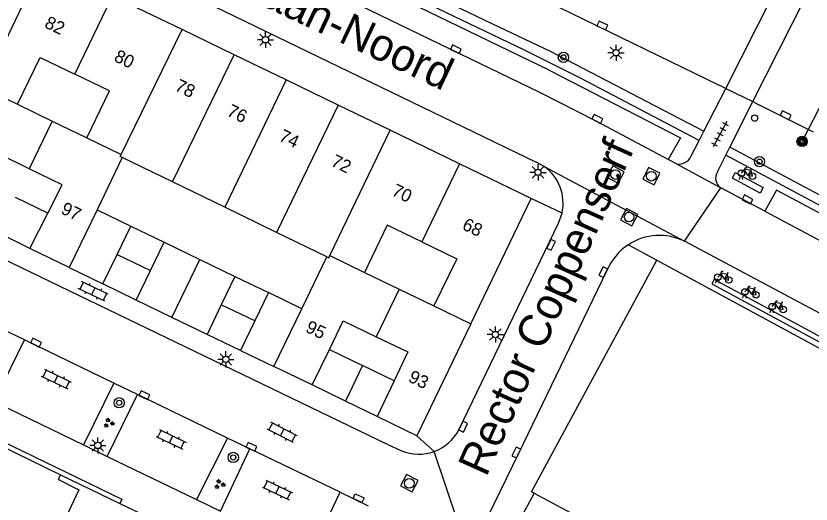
# Model space of a CAD drawing. Extents: x 132999 to 136000, y 398499 to 400501.
# Drawn here: x 134215 to 134276.8, y 398577.7 to 398615.7 of the extents above; entities that cross this region are included whole.
import ezdxf

# ---------------------------------------------------------------- set-up
doc = ezdxf.new("R2010")
doc.units = 0
for name, color, linetype in [('gg-afsc-muur', 7, 'Continuous'), ('gg-anno-huisnummerreeks BGT', 7, 'Continuous'), ('gg-anno-openbare ruimte label', 7, 'Continuous'), ('gg-bbg-bijgebouw', 7, 'Continuous'), ('gg-bbg-gedigitaliseerde bebouwing', 7, 'Continuous'), ('gg-bbg-gedigitaliseerde bijgebouw', 7, 'Continuous'), ('gg-bbg-hoofdgebouw', 7, 'Continuous'), ('gg-bbg-luifel en loopbrug', 7, 'Continuous'), ('gg-bbg-tussenscheiding', 7, 'Continuous'), ('gg-knt-verharding', 7, 'Continuous'), ('gg-knt-verharding nz', 7, 'Continuous'), ('gt-grn-groengrens', 7, 'Continuous'), ('gt-grn-weggrens', 7, 'Continuous'), ('gt-knt-lijn portaal', 7, 'Continuous'), ('gt-symb-boom', 7, 'Continuous'), ('gt-symb-fietsenrek', 7, 'Continuous'), ('gt-symb-groenvak', 7, 'Continuous'), ('gt-symb-klinker verharding', 7, 'Continuous'), ('gt-symb-kolk', 7, 'Continuous'), ('gt-symb-kolk center center', 7, 'Continuous'), ('gt-symb-lichtmast', 7, 'Continuous'), ('gt-symb-portaalmast', 7, 'Continuous'), ('gt-symb-rioolschacht', 7, 'Continuous'), ('gt-symb-tegel verharding', 7, 'Continuous'), ('gt-symb-verkeersregelinstallatiepaal', 7, 'Continuous')]:
    doc.layers.add(name, color=color, linetype=linetype)

# ---------------------------------------------------------------- blocks, each defined once
blk = doc.blocks.new('gt0-KOLK')
at = {"layer": 'gt-symb-kolk'}
blk.add_lwpolyline([(0, 0), (0.375, 0), (0.375, 0.4), (-0.375, 0.4), (-0.375, 0), (0, 0)], dxfattribs=at)
blk = doc.blocks.new('gt0-KL1')
at = {"layer": 'gt-symb-klinker verharding'}
for p, q in [((-1.15, 0.3), (1.15, 0.3)), ((-1, -0.3), (-1, 0.3)), ((-0.5, 0.3), (-0.5, 0.45)), ((0, -0.3), (0, 0.3)), ((0.5, 0.3), (0.5, 0.45)), ((1, -0.3), (1, 0.3)), ((-1.15, -0.3), (1.15, -0.3)), ((-0.5, -0.45), (-0.5, -0.3)), ((0.5, -0.45), (0.5, -0.3))]:
    blk.add_line(p, q, dxfattribs=at)
blk = doc.blocks.new('gt0-LMAST')
at = {"layer": 'gt-symb-lichtmast'}
for p, q in [((-0.005, 0.246), (-0.005, 0.621)), ((-0.182, 0.173), (-0.447, 0.438)), ((0.172, 0.173), (0.437, 0.438)), ((-0.255, -0.004), (-0.63, -0.004)), ((-0.182, -0.181), (-0.447, -0.446)), ((-0.005, -0.254), (-0.005, -0.629)), ((0.437, -0.446), (0.172, -0.181)), ((0.245, -0.004), (0.62, -0.004))]:
    blk.add_line(p, q, dxfattribs=at)
blk.add_circle((-0.005, -0.004), 0.25, dxfattribs=at)
blk = doc.blocks.new('gt0-GRVAK')
at = {"layer": 'gt-symb-groenvak'}
for p, q in [((-0.11, 0.189), (-0.228, 0.24)), ((-0.182, 0.153), (0.088, 0.153)), ((-0.091, 0.211), (-0.156, 0.322)), ((-0.047, 0.214), (-0.047, 0.393)), ((-0.004, 0.211), (0.061, 0.322)), ((0.015, 0.189), (0.133, 0.24)), ((0.262, -0.052), (0.197, 0.059)), ((0.305, -0.049), (0.305, 0.13)), ((0.349, -0.052), (0.414, 0.059)), ((-0.245, -0.228), (-0.363, -0.177)), ((-0.318, -0.264), (-0.047, -0.264)), ((-0.226, -0.206), (-0.291, -0.095)), ((-0.183, -0.203), (-0.183, -0.024)), ((-0.139, -0.206), (-0.074, -0.095)), ((-0.12, -0.228), (-0.002, -0.177)), ((0.243, -0.074), (0.125, -0.023)), ((0.17, -0.11), (0.441, -0.11)), ((0.368, -0.074), (0.486, -0.023))]:
    blk.add_line(p, q, dxfattribs=at)
blk = doc.blocks.new('gt0-BOOM')
at = {"layer": 'gt-symb-boom'}
for radius in [0.4, 0.2]:
    blk.add_circle((0, 0), radius, dxfattribs=at)
blk = doc.blocks.new('gt0-PORTM')
at = {"layer": 'gt-symb-portaalmast'}
for radius in [0.4, 0.33, 0.27, 0.21, 0.15]:
    blk.add_circle((0, 0), radius, dxfattribs=at)
blk = doc.blocks.new('gt0-TEG1')
at = {"layer": 'gt-symb-tegel verharding'}
for p, q in [((-1.125, 0), (1.125, 0)), ((-0.9, -0.25), (-0.9, 0.25)), ((-0.45, -0.25), (-0.45, 0.25)), ((0, -0.25), (0, 0.25)), ((0.45, -0.25), (0.45, 0.25)), ((0.9, -0.25), (0.9, 0.25))]:
    blk.add_line(p, q, dxfattribs=at)
blk = doc.blocks.new('gt0-FREK')
at = {"layer": 'gt-symb-fietsenrek'}
for p, q in [((0.259, 0.762), (0.294, 0.823)), ((0.54, 0.335), (0.259, 0.762)), ((0.294, 0.823), (0.767, 0.714)), ((0.767, 0.714), (0.54, 0.335)), ((0.757, 0.841), (0.866, 0.816)), ((0.767, 0.714), (0.84, 0.822)), ((0.895, 0.252), (0.767, 0.714))]:
    blk.add_line(p, q, dxfattribs=at)
for points in [[(0.036, 0.476), (0.228, 0.708), (0.259, 0.762)], [(0.294, 0.823), (0.36, 0.937), (0.452, 0.935)], [(-0.124, 0), (-0.047, 0.312), (0.053, 0.312), (0.12, 0)], [(0.54, 0.335), (0.555, 0.305), (0.895, 0.252)]]:
    blk.add_lwpolyline(points, dxfattribs=at)
for centre in [(0.036, 0.476), (0.895, 0.252)]:
    blk.add_circle(centre, 0.252, dxfattribs=at)
blk = doc.blocks.new('gt0-VIPAAL')
at = {"layer": 'gt-symb-verkeersregelinstallatiepaal'}
blk.add_circle((0, 0), 0.25, dxfattribs=at)
blk = doc.blocks.new('gt0-RS')
at = {"layer": 'gt-symb-rioolschacht'}
blk.add_lwpolyline([(-0.5, -0.5), (0.5, -0.5), (0.5, 0.5), (-0.5, 0.5)], close=True, dxfattribs=at)
blk.add_circle((0, 0), 0.375, dxfattribs=at)
blk = doc.blocks.new('gt0-KOLKCC')
at = {"layer": 'gt-symb-kolk center center'}
blk.add_lwpolyline([(-0.375, 0.2), (0.375, 0.2), (0.375, -0.2), (-0.375, -0.2)], close=True, dxfattribs=at)

msp = doc.modelspace()

# ---------------------------------------------------------------- linework, layer by layer
at = {"layer": 'gg-afsc-muur'}
for p, q in [((134218.437, 398579.968), (134223.046, 398577.746)), ((134223.046, 398577.746), (134224.741, 398576.929))]:
    msp.add_line(p, q, dxfattribs=at)
at = {"layer": 'gg-bbg-bijgebouw'}
for p, q in [((134217.447, 398600.328), (134214.917, 398601.556)), ((134222.838, 398597.119), (134223.9, 398599.316)), ((134223.9, 398599.316), (134226.497, 398598.061)), ((134216.054, 398597.583), (134213.575, 398598.785)), ((134221.724, 398594.814), (134222.838, 398597.119)), ((134232.007, 398595.398), (134234.609, 398594.14)), ((134224.321, 398593.558), (134221.724, 398594.814)), ((134234.609, 398594.14), (134233.547, 398591.943)), ((134233.547, 398591.943), (134232.433, 398589.637)), ((134232.433, 398589.637), (134229.831, 398590.895)), ((134239.35, 398589.721), (134241.929, 398588.47)), ((134244.387, 398587.276), (134241.929, 398588.47)), ((134240.594, 398585.707), (134238.025, 398586.956)), ((134243.063, 398584.513), (134240.594, 398585.707))]:
    msp.add_line(p, q, dxfattribs=at)
at = {"layer": 'gg-bbg-gedigitaliseerde bebouwing'}
for p, q in [((134215.092, 398608.801), (134217.791, 398607.491)), ((134217.791, 398607.491), (134220.49, 398606.181)), ((134242.09, 398595.718), (134244.791, 398594.413)), ((134244.791, 398594.413), (134247.492, 398593.108))]:
    msp.add_line(p, q, dxfattribs=at)
for points in [[(134215.092, 398608.801), (134216.845, 398612.441), (134219.546, 398611.136)], [(134220.49, 398606.181), (134222.247, 398609.831), (134219.546, 398611.136)], [(134246.558, 398598.084), (134243.857, 398599.389), (134242.09, 398595.718)], [(134246.558, 398598.084), (134249.26, 398596.779), (134247.492, 398593.108)]]:
    msp.add_lwpolyline(points, dxfattribs=at)
at = {"layer": 'gg-bbg-gedigitaliseerde bijgebouw'}
for p, q in [((134225.435, 398595.863), (134226.497, 398598.061)), ((134224.321, 398593.558), (134225.435, 398595.863)), ((134232.007, 398595.398), (134230.945, 398593.2)), ((134230.945, 398593.2), (134229.831, 398590.895))]:
    msp.add_line(p, q, dxfattribs=at)
at = {"layer": 'gg-bbg-hoofdgebouw'}
for p, q in [((134227.885, 398614.602), (134222.474, 398617.218)), ((134231.937, 398612.644), (134227.885, 398614.602)), ((134235.989, 398610.686), (134231.937, 398612.644)), ((134240.031, 398608.732), (134235.989, 398610.686)), ((134244.082, 398606.774), (134240.031, 398608.732)), ((134249.485, 398604.163), (134244.082, 398606.774)), ((134223.233, 398604.65), (134221.273, 398600.585)), ((134227.155, 398602.75), (134223.233, 398604.65)), ((134255.058, 398601.469), (134249.485, 398604.163)), ((134231.219, 398600.781), (134227.155, 398602.75)), ((134250.364, 398591.72), (134255.058, 398601.469)), ((134221.273, 398600.585), (134219.112, 398596.103)), ((134235.245, 398598.831), (134231.219, 398600.781)), ((134239.152, 398596.938), (134235.245, 398598.831)), ((134219.112, 398596.103), (134216.054, 398597.583)), ((134237.199, 398592.888), (134239.152, 398596.938)), ((134264.827, 398596.655), (134298.563, 398578.435)), ((134235.032, 398588.395), (134237.199, 398592.888)), ((134250.364, 398591.72), (134246.17, 398583.009)), ((134238.025, 398586.956), (134235.032, 398588.395)), ((134246.17, 398583.009), (134243.063, 398584.513)), ((134213.622, 398582.293), (134218.437, 398579.968)), ((134218.262, 398579.605), (134218.437, 398579.968))]:
    msp.add_line(p, q, dxfattribs=at)
for points in [[(134215.996, 398603.785), (134213.594, 398604.946), (134212.475, 398602.741)], [(134217.447, 398600.328), (134218.57, 398602.54), (134215.996, 398603.785)], [(134255.28, 398578.547), (134255.08, 398578.655), (134264.827, 398596.655)], [(134239.35, 398589.721), (134240.415, 398591.944), (134243.004, 398590.703)], [(134243.004, 398590.703), (134245.464, 398589.524), (134244.387, 398587.276)], [(134218.262, 398579.605), (134219.852, 398578.812), (134216.922, 398572.55), (134215.246, 398573.36)], [(134255.28, 398578.547), (134264.765, 398573.446), (134263.402, 398570.93), (134268.388, 398568.238), (134269.734, 398570.761), (134274.256, 398568.307), (134272.919, 398565.793), (134277.893, 398563.137), (134279.228, 398565.625), (134288.714, 398560.516)]]:
    msp.add_lwpolyline(points, dxfattribs=at)
at = {"layer": 'gg-bbg-luifel en loopbrug'}
for p, q in [((134221.273, 398600.585), (134223.9, 398599.316)), ((134226.497, 398598.061), (134229.265, 398596.723)), ((134227.095, 398592.217), (134229.265, 398596.723)), ((134229.265, 398596.723), (134232.007, 398595.398)), ((134219.112, 398596.103), (134221.724, 398594.814)), ((134237.199, 398592.888), (134234.609, 398594.14)), ((134227.095, 398592.217), (134224.321, 398593.558)), ((134229.831, 398590.895), (134227.095, 398592.217)), ((134232.433, 398589.637), (134235.032, 398588.395))]:
    msp.add_line(p, q, dxfattribs=at)
at = {"layer": 'gg-bbg-tussenscheiding'}
for p, q in [((134217.071, 398619.829), (134212.395, 398610.111)), ((134219.546, 398611.136), (134222.474, 398617.218)), ((134223.15, 398604.89), (134227.885, 398614.602)), ((134227.155, 398602.75), (134231.937, 398612.644)), ((134235.989, 398610.686), (134231.219, 398600.781)), ((134212.395, 398610.111), (134215.092, 398608.801)), ((134240.031, 398608.732), (134235.245, 398598.831)), ((134217.791, 398607.491), (134215.996, 398603.785)), ((134239.392, 398597.022), (134244.082, 398606.774)), ((134220.49, 398606.181), (134223.15, 398604.89)), ((134249.485, 398604.163), (134246.558, 398598.084)), ((134216.054, 398597.583), (134217.447, 398600.328)), ((134222.838, 398597.119), (134225.435, 398595.863)), ((134239.392, 398597.022), (134242.09, 398595.718)), ((134244.791, 398594.413), (134243.004, 398590.703)), ((134233.547, 398591.943), (134230.945, 398593.2)), ((134247.492, 398593.108), (134250.364, 398591.72)), ((134238.025, 398586.956), (134239.35, 398589.721)), ((134241.929, 398588.47), (134240.594, 398585.707)), ((134244.387, 398587.276), (134243.063, 398584.513))]:
    msp.add_line(p, q, dxfattribs=at)
for points in [[(134223.233, 398604.65), (134223.071, 398604.728), (134223.15, 398604.89)], [(134239.152, 398596.938), (134239.314, 398596.86), (134239.392, 398597.022)]]:
    msp.add_lwpolyline(points, dxfattribs=at)
at = {"layer": 'gg-knt-verharding'}
for p, q in [((134256.456, 398611.459), (134127.119, 398673.952)), ((134254.48, 398613.034), (134127.702, 398674.265)), ((134270.189, 398610.03), (134269.737, 398610.247)), ((134268.493, 398606.699), (134270.189, 398610.03)), ((134270.189, 398610.03), (134272.304, 398609.001)), ((134270.513, 398605.454), (134272.304, 398609.001)), ((134272.304, 398609.001), (134272.779, 398608.761)), ((134277.012, 398606.615), (134272.779, 398608.761)), ((134268.122, 398605.971), (134268.493, 398606.699)), ((134267.49, 398604.731), (134268.122, 398605.971)), ((134270.197, 398604.829), (134270.513, 398605.454)), ((134269.552, 398603.547), (134270.197, 398604.829)), ((134311.335, 398582.846), (134270.197, 398604.829)), ((134256.076, 398603.957), (134255.434, 398604.287)), ((134266.352, 398604.162), (134265.725, 398604.501)), ((134266.352, 398604.162), (134269.805, 398602.294)), ((134273.245, 398600.467), (134269.805, 398602.294)), ((134257.457, 398600.335), (134255.058, 398601.469)), ((134262.615, 398597.867), (134264.827, 398596.655)), ((134215.617, 398590.464), (134213.891, 398591.296)), ((134213.265, 398585.667), (134215.617, 398590.464)), ((134222.568, 398587.101), (134215.617, 398590.464)), ((134222.568, 398587.101), (134220.225, 398582.29)), ((134224.41, 398586.209), (134222.568, 398587.101)), ((134222.054, 398581.386), (134224.41, 398586.209)), ((134231.429, 398582.818), (134224.41, 398586.209)), ((134231.429, 398582.818), (134229.019, 398578.047)), ((134233.156, 398581.984), (134231.429, 398582.818)), ((134243.841, 398582.359), (134244.961, 398581.833)), ((134220.225, 398582.29), (134222.054, 398581.386)), ((134230.869, 398577.15), (134233.156, 398581.984)), ((134240.2, 398578.626), (134233.156, 398581.984)), ((134237.852, 398573.781), (134240.2, 398578.626)), ((134240.2, 398578.626), (134242.376, 398577.548)), ((134229.019, 398578.047), (134230.869, 398577.15)), ((134255.28, 398578.547), (134253.371, 398575.002))]:
    msp.add_line(p, q, dxfattribs=at)
for points in [[(134123.324, 398668.128), (134220.648, 398621.136), (134255.434, 398604.287)], [(134110.068, 398647.004), (134155.388, 398625.063), (134243.841, 398582.359)], [(134200.213, 398643.926), (134220.685, 398634.147), (134269.737, 398610.247)], [(134268.122, 398605.971), (134258.889, 398610.827), (134254.48, 398613.034)], [(134256.456, 398611.459), (134266.685, 398606.198), (134265.725, 398604.501)], [(134308.099, 398581.865), (134309.009, 398583.546), (134274.155, 398602.111), (134273.245, 398600.467)], [(134249.43, 398583.468), (134257.186, 398599.557), (134257.457, 398600.335)], [(134336.663, 398560.948), (134299.764, 398580.676), (134266.984, 398598.135)], [(134260.954, 398595.862), (134254.08, 398581.62), (134250.227, 398573.736)], [(134213.622, 398582.293), (134213.783, 398582.626), (134223.202, 398578.07), (134223.046, 398577.746)]]:
    msp.add_lwpolyline(points, dxfattribs=at)
for centre, radius, start, end in [((134266.527, 398605.234), 1.086, 260.7252, 332.4049), ((134254.015, 398601.097), 3.525, 347.51586, 54.22594), ((134270.326, 398603.051), 0.919, 147.34646, 235.48437), ((134265.035, 398594.17), 4.419, 63.82052, 123.19987), ((134265.039, 398594.168), 4.422, 123.24005, 157.48128), ((134246.297, 398585.111), 3.537, 290.06963, 332.3318), ((134246.294, 398585.113), 3.541, 247.88098, 290.09702)]:
    msp.add_arc(centre, radius, start, end, dxfattribs=at)
at = {"layer": 'gg-knt-verharding nz'}
for p, q in [((134270.189, 398610.03), (134274.748, 398619.02)), ((134272.304, 398609.001), (134276.827, 398617.969)), ((134213.265, 398585.667), (134220.225, 398582.29)), ((134222.054, 398581.386), (134229.019, 398578.047))]:
    msp.add_line(p, q, dxfattribs=at)
for points in [[(134255.735, 398609.702), (134198.876, 398637.194), (134126.254, 398672.227)], [(134265.725, 398604.501), (134260.109, 398607.482), (134255.735, 398609.702)], [(134272.879, 398601.879), (134270.709, 398603.06), (134270.93, 398603.498), (134273.1, 398602.317), (134272.879, 398601.879)], [(134273.245, 398600.467), (134289.939, 398591.59), (134308.099, 398581.865)], [(134269.115, 398594.827), (134289.801, 398583.655), (134289.982, 398583.99), (134269.296, 398595.162), (134269.115, 398594.827)]]:
    msp.add_lwpolyline(points, dxfattribs=at)
at = {"layer": 'gt-grn-groengrens'}
msp.add_line((134311.668, 398583.462), (134270.513, 398605.454), dxfattribs=at)
msp.add_lwpolyline([(134197.263, 398641.53), (134226.169, 398627.587), (134237.199, 398622.193), (134252.051, 398615.044), (134256.521, 398612.928), (134268.493, 398606.699)], dxfattribs=at)
at = {"layer": 'gt-grn-weggrens'}
for p, q in [((134256.076, 398603.957), (134266.984, 398598.135)), ((134266.984, 398598.135), (134269.805, 398602.294)), ((134246.17, 398583.009), (134247.511, 398581.788)), ((134250.227, 398573.736), (134247.511, 398581.788))]:
    msp.add_line(p, q, dxfattribs=at)
at = {"layer": 'gt-knt-lijn portaal'}
msp.add_line((134276.139, 398605.909), (134280.694, 398614.793), dxfattribs=at)

# ---------------------------------------------------------------- block references
at = {"layer": 'gt-symb-boom'}
for p in [(134257.564, 398612.446), (134272.823, 398604.331)]:
    msp.add_blockref('gt0-BOOM', p, dxfattribs=at)
for p, rotation in [((134223, 398585.573), -25.591424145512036), ((134231.874, 398581.318), -25.591424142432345)]:
    msp.add_blockref('gt0-BOOM', p, dxfattribs=dict(at, rotation=rotation))
at = {"layer": 'gt-symb-fietsenrek'}
for p in [(134271.377, 398602.953), (134269.548, 398594.872), (134271.654, 398593.72), (134273.765, 398592.578)]:
    msp.add_blockref('gt0-FREK', p, dxfattribs=at)
at = {"layer": 'gt-symb-groenvak'}
for p in [(134222.178, 398583.996), (134230.799, 398579.228)]:
    msp.add_blockref('gt0-GRVAK', p, dxfattribs=at)
at = {"layer": 'gt-symb-klinker verharding'}
for p, rotation in [((134220.966, 398594.237), 154.40857585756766), ((134218.101, 398587.418), -25.847610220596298), ((134235.68, 398583.272), 152.74312822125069), ((134227.032, 398582.722), -25.796026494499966), ((134235.318, 398578.794), -25.46334506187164)]:
    msp.add_blockref('gt0-KL1', p, dxfattribs=dict(at, rotation=rotation))
at = {"layer": 'gt-symb-kolk'}
for p, rotation in [((134260.51, 398614.743), -25.975714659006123), ((134249.102, 398612.898), -25.71951295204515), ((134274.772, 398607.769), -27.256871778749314), ((134260.109, 398607.482), -27.97472991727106), ((134271.793, 398601.218), -28.4366286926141), ((134256.424, 398597.946), -115.7960264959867), ((134260.844, 398595.644), 63.25557979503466), ((134216.429, 398590.072), -25.847610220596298), ((134224.867, 398585.988), -25.796026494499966), ((134249.589, 398583.797), -115.79602649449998), ((134233.202, 398581.962), -25.46334506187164), ((134254.08, 398581.62), 64.28048704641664)]:
    msp.add_blockref('gt0-KOLK', p, dxfattribs=dict(at, rotation=rotation))
at = {"layer": 'gt-symb-kolk center center', "rotation": -25.07917899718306}
msp.add_blockref('gt0-KOLKCC', (134241.623, 398578.152), dxfattribs=at)
at = {"layer": 'gt-symb-lichtmast'}
for p in [(134234.382, 398613.818), (134261.661, 398612.81), (134255.591, 398603.505), (134252.271, 398590.881), (134231.306, 398588.954), (134221.334, 398582.258)]:
    msp.add_blockref('gt0-LMAST', p, dxfattribs=at)
at = {"layer": 'gt-symb-portaalmast'}
msp.add_blockref('gt0-PORTM', (134276.139, 398605.909), dxfattribs=at)
at = {"layer": 'gt-symb-rioolschacht'}
for p, rotation in [((134261.614, 398603.331), 62.87123394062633), ((134264.406, 398603.2), -116.23193993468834), ((134262.676, 398600.018), 61.5129928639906), ((134245.574, 398579.309), -27.846622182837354)]:
    msp.add_blockref('gt0-RS', p, dxfattribs=dict(at, rotation=rotation))
at = {"layer": 'gt-symb-tegel verharding', "rotation": -118.10282356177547}
msp.add_blockref('gt0-TEG1', (134269.74, 398606.472), dxfattribs=at)
at = {"layer": 'gt-symb-verkeersregelinstallatiepaal', "rotation": -29.139261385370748}
msp.add_blockref('gt0-VIPAAL', (134272.448, 398607.723), dxfattribs=at)

# ---------------------------------------------------------------- texts
at = {"layer": 'gg-anno-huisnummerreeks BGT'}
for s, rotation, p in [('82', 334.2, (134217.114, 398614.811)), ('80', 334.2, (134222.521, 398612.197)), ('78', 334.2, (134227.253, 398609.91)), ('76', 334.2, (134231.305, 398607.952)), ('74', 334.2, (134235.351, 398605.996)), ('72', 334.2, (134239.399, 398604.04)), ('70', 334.2, (134244.125, 398601.756)), ('97', 334.2, (134218.384, 398600.343)), ('68', 334.2, (134249.612, 398599.104)), ('95', 334.3, (134237.423, 398591.129)), ('93', 334.2, (134245.423, 398587.259))]:
    msp.add_text(s, height=1, rotation=rotation, dxfattribs=at).set_placement(p)
at = {"layer": 'gg-anno-openbare ruimte label'}
for s, rotation, p in [('Ringbaan-Noord', 334.7, (134226.019, 398620.307)), ('Rector Coppenserf', 65.7, (134251.555, 398579.73))]:
    msp.add_text(s, height=2.5, rotation=rotation, dxfattribs=at).set_placement(p)

doc.saveas('drawing.dxf')
